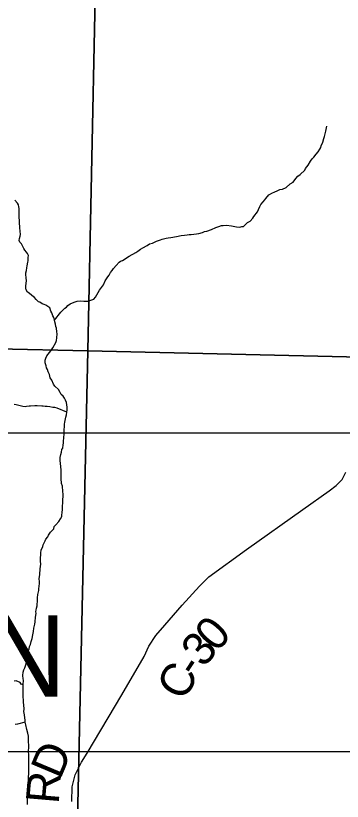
# Model space of a CAD drawing. Extents: x 0 to 34, y -2.3 to 22.
# Drawn here: x 4.214 to 4.776, y 16.601 to 17.952 of the extents above; entities that cross this region are included whole.
import ezdxf

# ---------------------------------------------------------------- set-up
doc = ezdxf.new("R2010")
doc.units = 0
for name, color, linetype in [('GM_X_County_Road', 7, 'Continuous'), ('GM_X_County_Road_Text', 7, 'Continuous'), ('GM_X_Minor_River', 7, 'Continuous'), ('GM_X_Section', 7, 'Continuous'), ('SH_Text', 7, 'Continuous')]:
    doc.layers.add(name, color=color, linetype=linetype)

msp = doc.modelspace()

# ---------------------------------------------------------------- linework, layer by layer
at = {"layer": 'GM_X_County_Road'}
for p, q in [((4.7754, 17.1541), (4.7822, 17.1668)), ((4.7654, 17.1438), (4.7754, 17.1541)), ((4.7533, 17.1346), (4.7654, 17.1438)), ((4.7081, 17.1027), (4.7533, 17.1346)), ((4.6112, 17.0339), (4.7081, 17.1027)), ((4.5464, 16.9868), (4.6112, 17.0339)), ((4.5301, 16.9706), (4.5464, 16.9868)), ((4.5007, 16.9378), (4.5301, 16.9706)), ((4.4705, 16.9037), (4.5007, 16.9378)), ((4.4552, 16.8857), (4.4705, 16.9037)), ((4.4435, 16.8674), (4.4552, 16.8857)), ((4.435, 16.8499), (4.4435, 16.8674)), ((4.3968, 16.7836), (4.435, 16.8499)), ((4.3373, 16.6833), (4.3968, 16.7836)), ((4.3273, 16.6679), (4.3373, 16.6833)), ((4.3164, 16.6462), (4.3273, 16.6679)), ((4.3114, 16.6253), (4.3164, 16.6462)), ((4.3106, 16.6), (4.3114, 16.6253))]:
    msp.add_line(p, q, dxfattribs=at)
at = {"layer": 'GM_X_Minor_River'}
for p, q in [((4.7481, 17.7564), (4.7489, 17.7591)), ((4.7489, 17.7591), (4.7494, 17.7617)), ((4.7442, 17.7406), (4.7451, 17.744)), ((4.7451, 17.744), (4.7473, 17.7534)), ((4.7473, 17.7534), (4.7481, 17.7564)), ((4.7397, 17.7282), (4.7425, 17.7346)), ((4.7425, 17.7346), (4.7442, 17.7406)), ((4.7309, 17.714), (4.7341, 17.7177)), ((4.7341, 17.7177), (4.7372, 17.7222)), ((4.7372, 17.7222), (4.7388, 17.7252)), ((4.7388, 17.7252), (4.7397, 17.7282)), ((4.7211, 17.7018), (4.7238, 17.7059)), ((4.7238, 17.7059), (4.7269, 17.7084)), ((4.7269, 17.7084), (4.7309, 17.714)), ((4.7127, 17.6891), (4.7174, 17.6951)), ((4.7174, 17.6951), (4.7211, 17.7018)), ((4.6994, 17.6758), (4.7033, 17.6788)), ((4.7033, 17.6788), (4.7115, 17.6865)), ((4.7115, 17.6865), (4.7127, 17.6891)), ((4.6791, 17.6563), (4.6861, 17.6629)), ((4.6861, 17.6629), (4.6915, 17.6658)), ((4.6915, 17.6658), (4.6962, 17.6721)), ((4.6962, 17.6721), (4.6994, 17.6758)), ((4.6587, 17.6486), (4.6652, 17.6514)), ((4.6652, 17.6514), (4.6687, 17.6528)), ((4.6687, 17.6528), (4.6729, 17.6538)), ((4.6729, 17.6538), (4.6791, 17.6563)), ((4.6427, 17.635), (4.6443, 17.6376)), ((4.6443, 17.6376), (4.6498, 17.6439)), ((4.6498, 17.6439), (4.656, 17.6471)), ((4.656, 17.6471), (4.6587, 17.6486)), ((4.2176, 17.6295), (4.2128, 17.6349)), ((4.219, 17.6268), (4.2176, 17.6295)), ((4.2197, 17.6233), (4.219, 17.6268)), ((4.2203, 17.6203), (4.2197, 17.6233)), ((4.6316, 17.6186), (4.634, 17.6239)), ((4.634, 17.6239), (4.636, 17.6272)), ((4.636, 17.6272), (4.6396, 17.632)), ((4.6396, 17.632), (4.6427, 17.635)), ((4.2201, 17.6112), (4.2203, 17.6203)), ((4.2203, 17.6051), (4.2201, 17.6112)), ((4.6236, 17.6063), (4.6299, 17.6145)), ((4.6299, 17.6145), (4.6316, 17.6186)), ((4.2209, 17.5997), (4.2203, 17.6051)), ((4.2211, 17.5937), (4.2209, 17.5997)), ((4.6088, 17.5923), (4.6131, 17.5964)), ((4.6131, 17.5964), (4.6173, 17.5985)), ((4.6173, 17.5985), (4.622, 17.6037)), ((4.622, 17.6037), (4.6236, 17.6063)), ((4.2214, 17.5899), (4.2211, 17.5937)), ((4.2216, 17.5868), (4.2214, 17.5899)), ((4.2222, 17.5811), (4.2216, 17.5868)), ((4.5427, 17.5814), (4.5511, 17.5842)), ((4.5511, 17.5842), (4.5585, 17.5878)), ((4.5585, 17.5878), (4.5634, 17.5891)), ((4.5634, 17.5891), (4.5681, 17.5909)), ((4.5681, 17.5909), (4.5711, 17.5912)), ((4.5711, 17.5912), (4.5768, 17.5914)), ((4.5768, 17.5914), (4.5855, 17.5907)), ((4.5855, 17.5907), (4.5938, 17.589)), ((4.5938, 17.589), (4.5995, 17.5884)), ((4.5995, 17.5884), (4.603, 17.5891)), ((4.603, 17.5891), (4.606, 17.5894)), ((4.606, 17.5894), (4.6088, 17.5923)), ((4.2206, 17.5652), (4.2207, 17.5686)), ((4.2207, 17.5686), (4.222, 17.5727)), ((4.222, 17.5727), (4.2225, 17.5758)), ((4.2225, 17.5758), (4.2222, 17.5811)), ((4.4663, 17.5673), (4.4728, 17.569)), ((4.4728, 17.569), (4.4766, 17.5701)), ((4.4766, 17.5701), (4.4812, 17.5707)), ((4.4812, 17.5707), (4.4911, 17.5723)), ((4.4911, 17.5723), (4.4991, 17.5736)), ((4.4991, 17.5736), (4.5045, 17.5742)), ((4.5045, 17.5742), (4.509, 17.5748)), ((4.509, 17.5748), (4.5125, 17.5755)), ((4.5125, 17.5755), (4.5163, 17.5753)), ((4.5163, 17.5753), (4.5254, 17.5766)), ((4.5254, 17.5766), (4.5293, 17.5772)), ((4.5293, 17.5772), (4.5354, 17.5793)), ((4.5354, 17.5793), (4.5389, 17.5807)), ((4.5389, 17.5807), (4.5427, 17.5814)), ((4.2213, 17.5625), (4.2206, 17.5652)), ((4.2243, 17.5594), (4.2213, 17.5625)), ((4.2282, 17.5517), (4.2243, 17.5594)), ((4.4328, 17.5528), (4.4405, 17.5567)), ((4.4405, 17.5567), (4.4444, 17.5593)), ((4.4444, 17.5593), (4.4493, 17.5606)), ((4.4493, 17.5606), (4.4563, 17.5642)), ((4.4563, 17.5642), (4.4632, 17.5663)), ((4.4632, 17.5663), (4.4663, 17.5673)), ((4.23, 17.5489), (4.2282, 17.5517)), ((4.233, 17.5454), (4.23, 17.5489)), ((4.2348, 17.5427), (4.233, 17.5454)), ((4.2362, 17.5393), (4.2348, 17.5427)), ((4.4092, 17.5383), (4.4211, 17.5448)), ((4.4211, 17.5448), (4.4242, 17.5469)), ((4.4242, 17.5469), (4.4289, 17.5506)), ((4.4289, 17.5506), (4.4328, 17.5528)), ((4.2342, 17.5215), (4.2351, 17.5279)), ((4.2351, 17.5279), (4.2356, 17.5305)), ((4.2356, 17.5305), (4.2358, 17.5362)), ((4.2358, 17.5362), (4.2362, 17.5393)), ((4.387, 17.5222), (4.3921, 17.5278)), ((4.3921, 17.5278), (4.3948, 17.5296)), ((4.3948, 17.5296), (4.3979, 17.531)), ((4.3979, 17.531), (4.4092, 17.5383)), ((4.2328, 17.5139), (4.2337, 17.5185)), ((4.2337, 17.5185), (4.2342, 17.5215)), ((4.3803, 17.5137), (4.3823, 17.517)), ((4.3823, 17.517), (4.387, 17.5222)), ((4.2316, 17.5098), (4.2328, 17.5139)), ((4.2319, 17.5071), (4.2316, 17.5098)), ((4.2324, 17.5003), (4.2319, 17.5071)), ((4.3684, 17.4958), (4.3728, 17.5029)), ((4.3728, 17.5029), (4.3751, 17.5055)), ((4.3751, 17.5055), (4.3775, 17.51)), ((4.3775, 17.51), (4.3803, 17.5137)), ((4.232, 17.4866), (4.2327, 17.4964)), ((4.2327, 17.4964), (4.2324, 17.5003)), ((4.3604, 17.4824), (4.3651, 17.4891)), ((4.3651, 17.4891), (4.3684, 17.4958)), ((4.2319, 17.4832), (4.232, 17.4866)), ((4.2322, 17.4805), (4.2319, 17.4832)), ((4.2348, 17.4766), (4.2322, 17.4805)), ((4.2378, 17.4746), (4.2348, 17.4766)), ((4.2422, 17.4707), (4.2378, 17.4746)), ((4.3516, 17.4678), (4.3564, 17.4757)), ((4.3564, 17.4757), (4.3584, 17.4798)), ((4.3584, 17.4798), (4.3604, 17.4824)), ((4.2467, 17.4672), (4.2422, 17.4707)), ((4.2496, 17.4637), (4.2467, 17.4672)), ((4.2533, 17.4597), (4.2496, 17.4637)), ((4.3149, 17.4594), (4.3198, 17.4608)), ((4.3198, 17.4608), (4.3259, 17.4614)), ((4.3259, 17.4614), (4.3316, 17.4608)), ((4.3316, 17.4608), (4.3358, 17.4607)), ((4.3358, 17.4607), (4.3385, 17.461)), ((4.3385, 17.461), (4.3454, 17.4631)), ((4.3454, 17.4631), (4.3488, 17.4645)), ((4.3488, 17.4645), (4.3516, 17.4678)), ((4.2559, 17.4589), (4.2533, 17.4597)), ((4.2597, 17.4561), (4.2559, 17.4589)), ((4.2634, 17.4549), (4.2597, 17.4561)), ((4.2664, 17.454), (4.2634, 17.4549)), ((4.2698, 17.452), (4.2664, 17.454)), ((4.2728, 17.4493), (4.2698, 17.452)), ((4.2749, 17.4439), (4.2728, 17.4493)), ((4.2958, 17.4459), (4.2986, 17.4489)), ((4.2986, 17.4489), (4.3017, 17.4507)), ((4.3017, 17.4507), (4.304, 17.4533)), ((4.304, 17.4533), (4.3079, 17.4562)), ((4.3079, 17.4562), (4.3149, 17.4594)), ((4.2767, 17.4408), (4.2749, 17.4439)), ((4.2781, 17.4358), (4.2767, 17.4408)), ((4.2799, 17.4327), (4.2781, 17.4358)), ((4.2813, 17.4281), (4.2919, 17.4419)), ((4.2919, 17.4419), (4.2958, 17.4459)), ((4.2813, 17.4281), (4.2799, 17.4327)), ((4.2816, 17.4255), (4.2813, 17.4281)), ((4.2826, 17.4216), (4.2816, 17.4255)), ((4.2836, 17.4174), (4.2826, 17.4216)), ((4.2847, 17.4144), (4.2836, 17.4174)), ((4.2852, 17.4079), (4.2847, 17.4144)), ((4.2855, 17.4045), (4.2852, 17.4079)), ((4.2832, 17.3897), (4.2848, 17.3931)), ((4.2848, 17.3931), (4.2853, 17.398)), ((4.2853, 17.398), (4.2855, 17.4045)), ((4.2748, 17.3755), (4.2784, 17.3807)), ((4.2784, 17.3807), (4.2832, 17.3897)), ((4.2661, 17.3629), (4.2681, 17.3666)), ((4.2681, 17.3666), (4.2701, 17.37)), ((4.2701, 17.37), (4.2748, 17.3755)), ((4.2651, 17.3549), (4.2652, 17.3595)), ((4.2668, 17.3496), (4.2651, 17.3549)), ((4.2652, 17.3595), (4.2661, 17.3629)), ((4.2675, 17.3465), (4.2668, 17.3496)), ((4.2693, 17.3434), (4.2675, 17.3465)), ((4.2703, 17.3396), (4.2693, 17.3434)), ((4.2725, 17.3346), (4.2703, 17.3396)), ((4.2738, 17.3292), (4.2725, 17.3346)), ((4.2764, 17.325), (4.2738, 17.3292)), ((4.2796, 17.318), (4.2764, 17.325)), ((4.2818, 17.3149), (4.2796, 17.318)), ((4.2877, 17.3091), (4.2818, 17.3149)), ((4.2906, 17.304), (4.2877, 17.3091)), ((4.2927, 17.3002), (4.2906, 17.304)), ((4.2957, 17.2974), (4.2927, 17.3002)), ((4.2983, 17.2943), (4.2957, 17.2974)), ((4.3001, 17.2905), (4.2983, 17.2943)), ((4.3018, 17.2866), (4.3001, 17.2905)), ((4.3025, 17.2828), (4.3018, 17.2866)), ((4.2154, 17.2823), (4.212, 17.2832)), ((4.2218, 17.2806), (4.2154, 17.2823)), ((4.2268, 17.2797), (4.2218, 17.2806)), ((4.2305, 17.2792), (4.2268, 17.2797)), ((4.2332, 17.2795), (4.2305, 17.2792)), ((4.2374, 17.2802), (4.2332, 17.2795)), ((4.2401, 17.2805), (4.2374, 17.2802)), ((4.2473, 17.281), (4.2401, 17.2805)), ((4.2515, 17.2809), (4.2473, 17.281)), ((4.2591, 17.2803), (4.2515, 17.2809)), ((4.2617, 17.2802), (4.2591, 17.2803)), ((4.2652, 17.2797), (4.2617, 17.2802)), ((4.2682, 17.2796), (4.2652, 17.2797)), ((4.2731, 17.2791), (4.2682, 17.2796)), ((4.2784, 17.2782), (4.2731, 17.2791)), ((4.2818, 17.2777), (4.2784, 17.2782)), ((4.2856, 17.2768), (4.2818, 17.2777)), ((4.3025, 17.2702), (4.2856, 17.2768)), ((4.3031, 17.2786), (4.3025, 17.2828)), ((4.3025, 17.2702), (4.303, 17.274)), ((4.303, 17.274), (4.3031, 17.2786)), ((4.2989, 17.2525), (4.3007, 17.2616)), ((4.3007, 17.2616), (4.3016, 17.2653)), ((4.3016, 17.2653), (4.3025, 17.2702)), ((4.2978, 17.2408), (4.2983, 17.2442)), ((4.2983, 17.2442), (4.2985, 17.2491)), ((4.2985, 17.2491), (4.2989, 17.2525)), ((4.297, 17.226), (4.2976, 17.2328)), ((4.2976, 17.2328), (4.2978, 17.2408)), ((4.2964, 17.2165), (4.2965, 17.2199)), ((4.2965, 17.2199), (4.297, 17.226)), ((4.2933, 17.2014), (4.2938, 17.2056)), ((4.2938, 17.2056), (4.2954, 17.2082)), ((4.2954, 17.2082), (4.2959, 17.2135)), ((4.2959, 17.2135), (4.2964, 17.2165)), ((4.2909, 17.1859), (4.2911, 17.192)), ((4.2911, 17.192), (4.292, 17.1972)), ((4.292, 17.1972), (4.2933, 17.2014)), ((4.2916, 17.1828), (4.2909, 17.1859)), ((4.2918, 17.1752), (4.2916, 17.1828)), ((4.2924, 17.1714), (4.2918, 17.1752)), ((4.2923, 17.1669), (4.2924, 17.1714)), ((4.2925, 17.1615), (4.2923, 17.1669)), ((4.2923, 17.1532), (4.2925, 17.1615)), ((4.2929, 17.1501), (4.2923, 17.1532)), ((4.2932, 17.1471), (4.2929, 17.1501)), ((4.2946, 17.1429), (4.2932, 17.1471)), ((4.2955, 17.1337), (4.2946, 17.1429)), ((4.2954, 17.1189), (4.296, 17.1257)), ((4.2957, 17.1291), (4.2955, 17.1337)), ((4.296, 17.1257), (4.2957, 17.1291)), ((4.295, 17.103), (4.2954, 17.1189)), ((4.2939, 17.0935), (4.2944, 17.0969)), ((4.2944, 17.0969), (4.295, 17.103)), ((4.2832, 17.076), (4.2887, 17.0819)), ((4.2887, 17.0819), (4.2915, 17.0867)), ((4.2915, 17.0867), (4.2935, 17.0905)), ((4.2935, 17.0905), (4.2939, 17.0935)), ((4.2744, 17.0637), (4.2799, 17.0692)), ((4.2799, 17.0692), (4.2804, 17.073)), ((4.2804, 17.073), (4.2832, 17.076)), ((4.2661, 17.0514), (4.2696, 17.0555)), ((4.2696, 17.0555), (4.2705, 17.0581)), ((4.2705, 17.0581), (4.2744, 17.0637)), ((4.2608, 17.039), (4.2616, 17.0417)), ((4.2616, 17.0417), (4.2652, 17.0484)), ((4.2652, 17.0484), (4.2661, 17.0514)), ((4.2573, 17.0251), (4.2574, 17.0281)), ((4.2574, 17.0281), (4.2583, 17.0326)), ((4.2583, 17.0326), (4.2608, 17.039)), ((4.2568, 17.019), (4.2573, 17.0251)), ((4.257, 17.0137), (4.2568, 17.019)), ((4.2566, 17.0004), (4.2573, 17.0087)), ((4.2573, 17.0087), (4.257, 17.0137)), ((4.2551, 16.9868), (4.2556, 16.9909)), ((4.2556, 16.9909), (4.2557, 16.9936)), ((4.2557, 16.9936), (4.2562, 16.9978)), ((4.2562, 16.9978), (4.2566, 17.0004)), ((4.2541, 16.9663), (4.2551, 16.9754)), ((4.255, 16.9837), (4.2551, 16.9868)), ((4.2552, 16.978), (4.255, 16.9837)), ((4.2551, 16.9754), (4.2552, 16.978)), ((4.2527, 16.9564), (4.254, 16.9632)), ((4.254, 16.9632), (4.2541, 16.9663)), ((4.2516, 16.9436), (4.2521, 16.9508)), ((4.2521, 16.9508), (4.2527, 16.9564)), ((4.2501, 16.9326), (4.251, 16.9367)), ((4.251, 16.9367), (4.2515, 16.9405)), ((4.2515, 16.9405), (4.2516, 16.9436)), ((4.2485, 16.9174), (4.2494, 16.9235)), ((4.2492, 16.9269), (4.2496, 16.9296)), ((4.2494, 16.9235), (4.2492, 16.9269)), ((4.2496, 16.9296), (4.2501, 16.9326)), ((4.2474, 16.9053), (4.2479, 16.9095)), ((4.2479, 16.9095), (4.2485, 16.9174)), ((4.2443, 16.8895), (4.2451, 16.8925)), ((4.2451, 16.8925), (4.2457, 16.8985)), ((4.2457, 16.8985), (4.2474, 16.9053)), ((4.2408, 16.8755), (4.2425, 16.8804)), ((4.2425, 16.8804), (4.2438, 16.8868)), ((4.2438, 16.8868), (4.2443, 16.8895)), ((4.2374, 16.8627), (4.2383, 16.8669)), ((4.2383, 16.8669), (4.2399, 16.8702)), ((4.2399, 16.8702), (4.2408, 16.8755)), ((4.2344, 16.8503), (4.2349, 16.8556)), ((4.2349, 16.8556), (4.2362, 16.8601)), ((4.2362, 16.8601), (4.2374, 16.8627)), ((4.232, 16.8351), (4.2338, 16.8442)), ((4.2338, 16.8442), (4.2339, 16.8472)), ((4.2339, 16.8472), (4.2344, 16.8503)), ((4.2271, 16.8227), (4.2284, 16.8265)), ((4.2284, 16.8265), (4.23, 16.8299)), ((4.23, 16.8299), (4.232, 16.8351)), ((4.2269, 16.8167), (4.2271, 16.8227)), ((4.2272, 16.8113), (4.2269, 16.8167)), ((4.2149, 16.8075), (4.2119, 16.8072)), ((4.2221, 16.805), (4.2149, 16.8075)), ((4.2235, 16.802), (4.2221, 16.805)), ((4.2272, 16.8007), (4.2235, 16.802)), ((4.227, 16.7927), (4.2272, 16.8007)), ((4.2275, 16.8087), (4.2272, 16.8113)), ((4.2272, 16.8007), (4.2275, 16.8087)), ((4.2272, 16.7859), (4.227, 16.7927)), ((4.2274, 16.7806), (4.2272, 16.7859)), ((4.228, 16.7737), (4.2274, 16.7806)), ((4.2279, 16.7707), (4.228, 16.7737)), ((4.2285, 16.7665), (4.2279, 16.7707)), ((4.2287, 16.7593), (4.2285, 16.7665)), ((4.2286, 16.7551), (4.2287, 16.7593)), ((4.2289, 16.7524), (4.2286, 16.7551)), ((4.2295, 16.749), (4.2289, 16.7524)), ((4.2298, 16.7444), (4.2295, 16.749)), ((4.2304, 16.7402), (4.2298, 16.7444)), ((4.2173, 16.7334), (4.2135, 16.7324)), ((4.2307, 16.7368), (4.2173, 16.7334)), ((4.2307, 16.7368), (4.2304, 16.7402)), ((4.2317, 16.7318), (4.2307, 16.7368)), ((4.2334, 16.7238), (4.2317, 16.7318)), ((4.2355, 16.7176), (4.2334, 16.7238)), ((4.2361, 16.7127), (4.2355, 16.7176)), ((4.2365, 16.7024), (4.2361, 16.7127)), ((4.2372, 16.6975), (4.2365, 16.7024)), ((4.2365, 16.6861), (4.2367, 16.6941)), ((4.2367, 16.6941), (4.2372, 16.6975)), ((4.2367, 16.6804), (4.2365, 16.6861)), ((4.2369, 16.6762), (4.2367, 16.6804)), ((4.2368, 16.672), (4.2369, 16.6762)), ((4.237, 16.6652), (4.2368, 16.672)), ((4.2371, 16.6572), (4.237, 16.6652)), ((4.2368, 16.6466), (4.2371, 16.6572)), ((4.2361, 16.6341), (4.2364, 16.6435)), ((4.2364, 16.6435), (4.2368, 16.6466)), ((4.2363, 16.6287), (4.2361, 16.6341)), ((4.2366, 16.6245), (4.2363, 16.6287)), ((4.2363, 16.6139), (4.2366, 16.6245)), ((4.2353, 16.6079), (4.2363, 16.6139)), ((4.2346, 16.595), (4.2348, 16.6029)), ((4.2348, 16.6029), (4.2353, 16.6079))]:
    msp.add_line(p, q, dxfattribs=at)
at = {"layer": 'GM_X_Section'}
for p, q in [((4.3586, 18.376), (4.3385, 17.3752)), ((4.3385, 17.3752), (4.3586, 18.376)), ((4.3385, 17.3752), (3.5407, 17.3953)), ((3.5407, 17.3953), (4.3385, 17.3752)), ((4.3385, 17.3752), (4.317, 16.3953)), ((4.317, 16.3953), (4.3385, 17.3752)), ((5.3441, 17.3523), (4.3385, 17.3752)), ((4.3385, 17.3752), (5.3441, 17.3523))]:
    msp.add_line(p, q, dxfattribs=at)
at = {"layer": 'SH_Text'}
msp.add_lwpolyline([(3.1803, 17.2342), (5.021, 17.2342), (5.021, 16.6854), (3.1803, 16.6854)], close=True, dxfattribs=at)

# ---------------------------------------------------------------- texts
at = {"layer": 'GM_X_County_Road_Text'}
for s, rotation, p in [('0', 48.2501, (4.5596, 16.8553)), ('3', 49.5954, (4.5372, 16.8289)), ('-', 57.0087, (4.5256, 16.8109)), ('C', 61.0072, (4.5036, 16.771)), ('D', 67.2091, (4.2909, 16.6369)), ('R', 85.1526, (4.2881, 16.5949))]:
    msp.add_text(s, height=0.0568, rotation=rotation, dxfattribs=at).set_placement(p)
at = {"layer": 'SH_Text'}
msp.add_text('LOCATION', height=0.14, dxfattribs=at).set_placement((3.3445, 16.7804))

doc.saveas('drawing.dxf')
